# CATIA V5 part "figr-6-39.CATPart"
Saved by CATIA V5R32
Part number: Part1
Bounding box of the stored display mesh (mm): x -43 to 43, y -66.608 to 66.608, z -13.545 to 13.545
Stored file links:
  D:\PROJECTS\Project 2022\CATIA V5 6R 2022\Resources\Part Files\c06_catia_v5_6r2022_prt\figr-6-39.CATPart
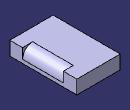
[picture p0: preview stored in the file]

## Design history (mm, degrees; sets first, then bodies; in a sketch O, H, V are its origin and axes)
Body1 (main body)
  Sketch1 on yz-plane, origin (0, 0, 0), H (0, 1, 0), V (0, 0, 1)
    line L1 (-66.6077, 13.5449) -> (66.6077, 13.5449)
    line L2 (66.6077, 13.5449) -> (66.6077, -13.5449)
    line L3 (66.6077, -13.5449) -> (-66.6077, -13.5449)
    line L4 (-66.6077, -13.5449) -> (-66.6077, 13.5449)
    axis line L5 (66.6077, -13.5449) -> (-66.6077, 13.5449)
    horizontal: L1 H, L3 H
    vertical: L2 V, L4 V
    midpoint: O L5
  Pad1: profile Sketch1, direction (1, 0, 0), length 43, mirrored extent
  Fillet1: radius 20, on edge [face of Pad1 | face of Pad1]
